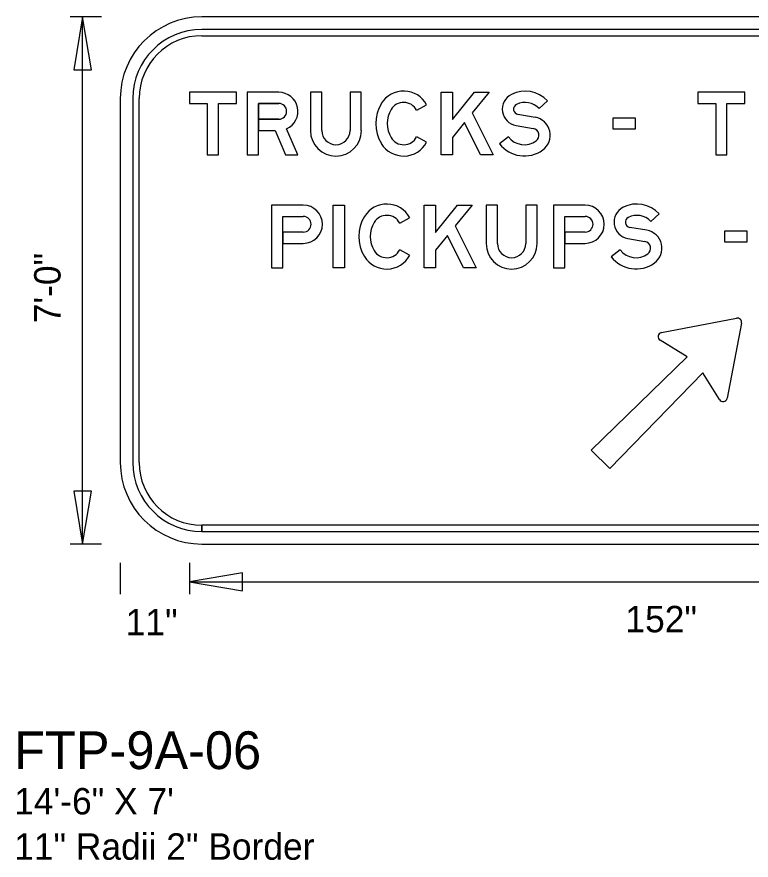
# Model space of a CAD drawing. Extents: x 0 to 770, y 0 to 495.
# Drawn here: x 391.7 to 488.9, y 9 to 120.7 of the extents above; entities that cross this region are included whole.
import ezdxf

# ---------------------------------------------------------------- set-up
doc = ezdxf.new("R2010")
doc.units = 0
for name, color, linetype in [('Dimension', 7, 'Continuous'), ('GSBWFill', 7, 'Continuous'), ('GSColorFill', 7, 'Continuous'), ('GSDims', 7, 'Continuous'), ('GSOutline', 7, 'Continuous'), ('TextStructures', 7, 'Continuous')]:
    doc.layers.add(name, color=color, linetype=linetype)

msp = doc.modelspace()

# ---------------------------------------------------------------- linework, layer by layer
at = {"layer": 'Dimension'}
for points in [[(400.45, 120.68), (399.27, 113.66), (401.64, 113.66)], [(400.45, 50.88), (401.64, 57.9), (399.27, 57.9)], [(414.58, 45.9), (421.6, 44.71), (421.6, 47.09)]]:
    msp.add_lwpolyline(points, close=True, dxfattribs=at)
at = {"layer": 'GSBWFill'}
for p, q in [((539.21, 120.68), (416.24, 120.68)), ((539.21, 119.01), (416.24, 119.01)), ((416.24, 118.18), (539.21, 118.18)), ((435.85, 110.71), (435.85, 105.62)), ((405.44, 109.87), (405.44, 61.68)), ((407.1, 109.87), (407.1, 61.68)), ((407.93, 61.68), (407.93, 109.87)), ((460.88, 108.54), (461.98, 109.56)), ((444.67, 108.32), (445.99, 109.02)), ((460.35, 107.37), (458.08, 107.75)), ((457.83, 106.28), (460.1, 105.9)), ((445.99, 104.08), (444.67, 104.78)), ((444.67, 104.78), (444.67, 104.78)), ((456.81, 104.78), (455.62, 103.87)), ((459.11, 95.75), (459.11, 90.66)), ((426.96, 94.25), (429.66, 94.25)), ((442.42, 93.36), (443.74, 94.07)), ((464.26, 94.25), (466.97, 94.25)), ((475.67, 93.59), (476.77, 94.61)), ((475.14, 92.42), (472.87, 92.8)), ((472.62, 91.32), (474.89, 90.94)), ((443.74, 89.12), (442.42, 89.83)), ((442.42, 89.83), (442.42, 89.83)), ((471.6, 89.83), (470.41, 88.92)), ((477.08, 78.87), (487.02, 80.78)), ((487.67, 80.14), (485.76, 70.19)), ((485.76, 70.19), (485.76, 70.19)), ((416.24, 52.54), (416.24, 53.38)), ((539.21, 53.38), (416.25, 53.38)), ((416.25, 53.38), (416.25, 52.54)), ((416.25, 52.54), (539.21, 52.54)), ((416.24, 50.88), (539.21, 50.88))]:
    msp.add_line(p, q, dxfattribs=at)
for points in [[(414.58, 109.21), (416.95, 109.21), (416.95, 102.4), (418.44, 102.4), (418.44, 109.21), (420.81, 109.21), (420.81, 110.71), (414.58, 110.71)], [(454.25, 110.71), (452.03, 107.96), (454.79, 102.4), (453.12, 102.4), (450.99, 106.69), (449.39, 104.72), (449.39, 102.4), (447.9, 102.4), (447.9, 110.71), (449.39, 110.71), (449.39, 107.09), (452.33, 110.71)], [(481.88, 109.21), (484.25, 109.21), (484.25, 102.4), (485.74, 102.4), (485.74, 109.21), (488.11, 109.21), (488.11, 110.71), (481.88, 110.71)], [(470.66, 107.3), (473.57, 107.3), (473.57, 105.8), (470.66, 105.8)], [(433.61, 87.44), (433.61, 95.75), (435.1, 95.75), (435.1, 87.44)], [(452.01, 95.75), (449.78, 93.01), (452.55, 87.44), (450.88, 87.44), (448.75, 91.73), (447.15, 89.77), (447.15, 87.44), (445.65, 87.44), (445.65, 95.75), (447.15, 95.75), (447.15, 92.14), (450.08, 95.75)], [(485.45, 92.34), (488.36, 92.34), (488.36, 90.85), (485.45, 90.85)]]:
    msp.add_lwpolyline(points, close=True, dxfattribs=at)
for points in [[(426.42, 110.71), (422.22, 110.71), (422.22, 102.4), (423.72, 102.4), (423.72, 109.21), (426.42, 109.21)], [(432.11, 105.62), (432.11, 110.71), (430.61, 110.71), (430.61, 105.62)], [(437.34, 105.62), (437.34, 110.71), (435.85, 110.71)], [(426.42, 107.13), (423.72, 107.13), (423.72, 105.64)], [(423.72, 105.64), (425.92, 105.64), (427.32, 102.4), (428.95, 102.4), (427.45, 105.86)], [(429.66, 95.75), (425.46, 95.75), (425.46, 87.44), (426.96, 87.44), (426.96, 94.25)], [(455.37, 90.66), (455.37, 95.75), (453.88, 95.75), (453.88, 90.66)], [(460.61, 90.66), (460.61, 95.75), (459.11, 95.75)], [(466.97, 95.75), (462.77, 95.75), (462.77, 87.44), (464.26, 87.44), (464.26, 94.25)], [(429.66, 92.18), (426.96, 92.18), (426.96, 90.68), (429.66, 90.68)], [(466.97, 92.18), (464.27, 92.18), (464.27, 90.68), (466.97, 90.68)], [(484.75, 70.01), (482.57, 73.57), (470.22, 60.88), (467.77, 63.33), (480.46, 75.68), (476.9, 77.86)]]:
    msp.add_lwpolyline(points, dxfattribs=at)
for centre, radius, start, end in [((416.24, 109.87), 10.8, 90, 180), ((416.24, 109.87), 9.14, 90, 180), ((416.24, 109.87), 8.31, 90, 180), ((459.03, 106.82), 4.03, 42.8759, 116.9123), ((458.2, 108.45), 2.2, 116.9123, 260.4087), ((458.2, 108.45), 0.706, 116.9123, 260.4087), ((459.03, 106.82), 2.53, 42.8759, 116.9123), ((459.94, 105), 2.41, 306.123, 80.4087), ((433.98, 105.62), 3.37, 180, 0), ((433.98, 105.62), 1.87, 180, 0), ((459.94, 105), 0.914, 306.123, 80.4087), ((458.92, 106.41), 4.15, 217.5895, 306.123), ((458.92, 106.41), 2.66, 217.5895, 306.123), ((429.66, 93.22), 2.53, 270, 90), ((472.99, 93.5), 2.2, 116.9123, 260.4087), ((473.82, 91.87), 4.03, 42.8759, 116.9123), ((429.66, 93.22), 1.04, 270, 90), ((472.99, 93.5), 0.706, 116.9123, 260.4087), ((473.82, 91.87), 2.53, 42.8759, 116.9123), ((474.73, 90.04), 2.41, 306.123, 80.4087), ((457.24, 90.66), 3.37, 180, 0), ((457.24, 90.66), 1.87, 180, 0), ((474.73, 90.04), 0.914, 306.123, 80.4087), ((473.71, 91.45), 2.66, 217.5895, 306.123), ((473.71, 91.45), 4.15, 217.5895, 306.123), ((487.13, 80.24), 0.551, 349.1228, 100.8772), ((477.18, 78.33), 0.551, 100.8772, 238.5281), ((485.22, 70.3), 0.551, 211.4719, 349.1228), ((416.24, 61.68), 10.8, 180, 270), ((416.24, 61.68), 9.14, 180, 270), ((416.24, 61.68), 8.31, 180, 270)]:
    msp.add_arc(centre, radius, start, end, dxfattribs=at)
for centre, major_axis, start_param, end_param in [((426.42, 108.17), (0, 2.53), 3.562504, 6.283185), ((442.94, 107.4), (0, 3.45), 5.201543, 7.308565), ((426.42, 108.17), (0, 1.04), 3.141593, 6.283185), ((444.35, 106.55), (0, 5.09), 1.025379, 2.116213), ((444.35, 106.55), (0, 3.59), 1.025379, 2.116213), ((442.94, 107.4), (0, 1.95), 5.201543, 7.308565), ((442.94, 105.7), (0, 3.45), 2.116213, 4.223235), ((442.94, 105.7), (0, 1.95), 2.116213, 4.223235), ((440.7, 92.45), (0, 3.45), 5.201543, 7.308565), ((466.97, 93.22), (0, 2.53), 3.141593, 6.283185), ((442.1, 91.6), (0, 5.09), 1.025379, 2.116213), ((440.7, 92.45), (0, 1.95), 5.201543, 7.308565), ((466.97, 93.22), (0, 1.04), 3.141593, 6.283185), ((442.1, 91.6), (0, 3.59), 1.025379, 2.116213), ((440.7, 90.74), (0, 1.95), 2.116213, 4.223235), ((440.7, 90.74), (0, 3.45), 2.116213, 4.223235)]:
    msp.add_ellipse(centre, major_axis=major_axis, ratio=0.999994, start_param=start_param, end_param=end_param, dxfattribs=at)
at = {"layer": 'GSColorFill'}
for p, q in [((435.85, 110.71), (435.85, 105.62)), ((460.88, 108.54), (461.98, 109.56)), ((444.67, 108.32), (445.99, 109.02)), ((460.35, 107.37), (458.08, 107.75)), ((457.83, 106.28), (460.1, 105.9)), ((445.99, 104.08), (444.67, 104.78)), ((444.67, 104.78), (444.67, 104.78)), ((456.81, 104.78), (455.62, 103.87)), ((459.11, 95.75), (459.11, 90.66)), ((426.96, 94.25), (429.66, 94.25)), ((442.42, 93.36), (443.74, 94.07)), ((464.26, 94.25), (466.97, 94.25)), ((475.67, 93.59), (476.77, 94.61)), ((475.14, 92.42), (472.87, 92.8)), ((472.62, 91.32), (474.89, 90.94)), ((443.74, 89.12), (442.42, 89.83)), ((442.42, 89.83), (442.42, 89.83)), ((471.6, 89.83), (470.41, 88.92)), ((477.08, 78.87), (487.02, 80.78)), ((487.67, 80.14), (485.76, 70.19)), ((485.76, 70.19), (485.76, 70.19))]:
    msp.add_line(p, q, dxfattribs=at)
for points in [[(414.58, 109.21), (416.95, 109.21), (416.95, 102.4), (418.44, 102.4), (418.44, 109.21), (420.81, 109.21), (420.81, 110.71), (414.58, 110.71)], [(454.25, 110.71), (452.03, 107.96), (454.79, 102.4), (453.12, 102.4), (450.99, 106.69), (449.39, 104.72), (449.39, 102.4), (447.9, 102.4), (447.9, 110.71), (449.39, 110.71), (449.39, 107.09), (452.33, 110.71)], [(481.88, 109.21), (484.25, 109.21), (484.25, 102.4), (485.74, 102.4), (485.74, 109.21), (488.11, 109.21), (488.11, 110.71), (481.88, 110.71)], [(470.66, 107.3), (473.57, 107.3), (473.57, 105.8), (470.66, 105.8)], [(433.61, 87.44), (433.61, 95.75), (435.1, 95.75), (435.1, 87.44)], [(452.01, 95.75), (449.78, 93.01), (452.55, 87.44), (450.88, 87.44), (448.75, 91.73), (447.15, 89.77), (447.15, 87.44), (445.65, 87.44), (445.65, 95.75), (447.15, 95.75), (447.15, 92.14), (450.08, 95.75)], [(485.45, 92.34), (488.36, 92.34), (488.36, 90.85), (485.45, 90.85)]]:
    msp.add_lwpolyline(points, close=True, dxfattribs=at)
for points in [[(426.42, 110.71), (422.22, 110.71), (422.22, 102.4), (423.72, 102.4), (423.72, 109.21), (426.42, 109.21)], [(432.11, 105.62), (432.11, 110.71), (430.61, 110.71), (430.61, 105.62)], [(437.34, 105.62), (437.34, 110.71), (435.85, 110.71)], [(426.42, 107.13), (423.72, 107.13), (423.72, 105.64)], [(423.72, 105.64), (425.92, 105.64), (427.32, 102.4), (428.95, 102.4), (427.45, 105.86)], [(429.66, 95.75), (425.46, 95.75), (425.46, 87.44), (426.96, 87.44), (426.96, 94.25)], [(455.37, 90.66), (455.37, 95.75), (453.88, 95.75), (453.88, 90.66)], [(460.61, 90.66), (460.61, 95.75), (459.11, 95.75)], [(466.97, 95.75), (462.77, 95.75), (462.77, 87.44), (464.26, 87.44), (464.26, 94.25)], [(429.66, 92.18), (426.96, 92.18), (426.96, 90.68), (429.66, 90.68)], [(466.97, 92.18), (464.27, 92.18), (464.27, 90.68), (466.97, 90.68)], [(484.75, 70.01), (482.57, 73.57), (470.22, 60.88), (467.77, 63.33), (480.46, 75.68), (476.9, 77.86)]]:
    msp.add_lwpolyline(points, dxfattribs=at)
for centre, radius, start, end in [((459.03, 106.82), 4.03, 42.8759, 116.9123), ((458.2, 108.45), 2.2, 116.9123, 260.4087), ((458.2, 108.45), 0.706, 116.9123, 260.4087), ((459.03, 106.82), 2.53, 42.8759, 116.9123), ((459.94, 105), 2.41, 306.123, 80.4087), ((433.98, 105.62), 3.37, 180, 0), ((433.98, 105.62), 1.87, 180, 0), ((459.94, 105), 0.914, 306.123, 80.4087), ((458.92, 106.41), 4.15, 217.5895, 306.123), ((458.92, 106.41), 2.66, 217.5895, 306.123), ((429.66, 93.22), 2.53, 270, 90), ((472.99, 93.5), 2.2, 116.9123, 260.4087), ((473.82, 91.87), 4.03, 42.8759, 116.9123), ((429.66, 93.22), 1.04, 270, 90), ((472.99, 93.5), 0.706, 116.9123, 260.4087), ((473.82, 91.87), 2.53, 42.8759, 116.9123), ((474.73, 90.04), 2.41, 306.123, 80.4087), ((457.24, 90.66), 3.37, 180, 0), ((457.24, 90.66), 1.87, 180, 0), ((474.73, 90.04), 0.914, 306.123, 80.4087), ((473.71, 91.45), 2.66, 217.5895, 306.123), ((473.71, 91.45), 4.15, 217.5895, 306.123), ((487.13, 80.24), 0.551, 349.1228, 100.8772), ((477.18, 78.33), 0.551, 100.8772, 238.5281), ((485.22, 70.3), 0.551, 211.4719, 349.1228)]:
    msp.add_arc(centre, radius, start, end, dxfattribs=at)
for centre, major_axis, start_param, end_param in [((426.42, 108.17), (0, 2.53), 3.562504, 6.283185), ((442.94, 107.4), (0, 3.45), 5.201543, 7.308565), ((426.42, 108.17), (0, 1.04), 3.141593, 6.283185), ((444.35, 106.55), (0, 5.09), 1.025379, 2.116213), ((444.35, 106.55), (0, 3.59), 1.025379, 2.116213), ((442.94, 107.4), (0, 1.95), 5.201543, 7.308565), ((442.94, 105.7), (0, 3.45), 2.116213, 4.223235), ((442.94, 105.7), (0, 1.95), 2.116213, 4.223235), ((440.7, 92.45), (0, 3.45), 5.201543, 7.308565), ((466.97, 93.22), (0, 2.53), 3.141593, 6.283185), ((442.1, 91.6), (0, 5.09), 1.025379, 2.116213), ((440.7, 92.45), (0, 1.95), 5.201543, 7.308565), ((466.97, 93.22), (0, 1.04), 3.141593, 6.283185), ((442.1, 91.6), (0, 3.59), 1.025379, 2.116213), ((440.7, 90.74), (0, 1.95), 2.116213, 4.223235), ((440.7, 90.74), (0, 3.45), 2.116213, 4.223235)]:
    msp.add_ellipse(centre, major_axis=major_axis, ratio=0.999994, start_param=start_param, end_param=end_param, dxfattribs=at)
at = {"layer": 'GSDims'}
for p, q in [((402.95, 120.68), (398.79, 120.68)), ((400.45, 50.88), (400.45, 120.68)), ((402.95, 50.88), (398.79, 50.88)), ((405.44, 48.39), (405.44, 44.24)), ((414.58, 48.39), (414.58, 44.24)), ((414.58, 48.39), (414.58, 44.24)), ((414.58, 45.9), (540.87, 45.9))]:
    msp.add_line(p, q, dxfattribs=at)
at = {"layer": 'GSOutline'}
for p, q in [((435.85, 110.71), (435.85, 105.62)), ((460.88, 108.54), (461.98, 109.56)), ((444.67, 108.32), (445.99, 109.02)), ((460.35, 107.37), (458.08, 107.75)), ((423.72, 107.13), (426.42, 107.13)), ((457.83, 106.28), (460.1, 105.9)), ((445.99, 104.08), (444.67, 104.78)), ((444.67, 104.78), (444.67, 104.78)), ((456.81, 104.78), (455.62, 103.87)), ((459.11, 95.75), (459.11, 90.66)), ((426.96, 94.25), (429.66, 94.25)), ((442.42, 93.36), (443.74, 94.07)), ((464.26, 94.25), (466.97, 94.25)), ((475.67, 93.59), (476.77, 94.61)), ((475.14, 92.42), (472.87, 92.8)), ((426.96, 90.68), (429.66, 90.68)), ((464.26, 90.68), (466.97, 90.68)), ((472.62, 91.32), (474.89, 90.94)), ((443.74, 89.12), (442.42, 89.83)), ((442.42, 89.83), (442.42, 89.83)), ((471.6, 89.83), (470.41, 88.92)), ((477.08, 78.87), (487.02, 80.78)), ((487.67, 80.14), (485.76, 70.19)), ((485.76, 70.19), (485.76, 70.19))]:
    msp.add_line(p, q, dxfattribs=at)
for points in [[(414.58, 109.21), (416.95, 109.21), (416.95, 102.4), (418.44, 102.4), (418.44, 109.21), (420.81, 109.21), (420.81, 110.71), (414.58, 110.71)], [(454.25, 110.71), (452.03, 107.96), (454.79, 102.4), (453.12, 102.4), (450.99, 106.69), (449.39, 104.72), (449.39, 102.4), (447.9, 102.4), (447.9, 110.71), (449.39, 110.71), (449.39, 107.09), (452.33, 110.71)], [(481.88, 109.21), (484.25, 109.21), (484.25, 102.4), (485.74, 102.4), (485.74, 109.21), (488.11, 109.21), (488.11, 110.71), (481.88, 110.71)], [(470.66, 107.3), (473.57, 107.3), (473.57, 105.8), (470.66, 105.8)], [(433.61, 87.44), (433.61, 95.75), (435.1, 95.75), (435.1, 87.44)], [(452.01, 95.75), (449.78, 93.01), (452.55, 87.44), (450.88, 87.44), (448.75, 91.73), (447.15, 89.77), (447.15, 87.44), (445.65, 87.44), (445.65, 95.75), (447.15, 95.75), (447.15, 92.14), (450.08, 95.75)], [(485.45, 92.34), (488.36, 92.34), (488.36, 90.85), (485.45, 90.85)]]:
    msp.add_lwpolyline(points, close=True, dxfattribs=at)
for points in [[(426.42, 110.71), (422.22, 110.71), (422.22, 102.4), (423.72, 102.4), (423.72, 105.64), (425.92, 105.64)], [(432.11, 105.62), (432.11, 110.71), (430.61, 110.71), (430.61, 105.62)], [(437.34, 105.62), (437.34, 110.71), (435.85, 110.71)], [(426.42, 109.21), (423.72, 109.21), (423.72, 107.13)], [(425.92, 105.64), (427.32, 102.4), (428.95, 102.4), (427.45, 105.86)], [(429.66, 95.75), (425.46, 95.75), (425.46, 87.44), (426.96, 87.44), (426.96, 90.68)], [(455.37, 90.66), (455.37, 95.75), (453.88, 95.75), (453.88, 90.66)], [(460.61, 90.66), (460.61, 95.75), (459.11, 95.75)], [(466.97, 95.75), (462.77, 95.75), (462.77, 87.44), (464.26, 87.44), (464.26, 90.68)], [(429.66, 92.18), (426.96, 92.18), (426.96, 94.25)], [(466.97, 92.18), (464.26, 92.18), (464.26, 94.25)], [(484.75, 70.01), (482.57, 73.57), (470.22, 60.88), (467.77, 63.33), (480.46, 75.68), (476.9, 77.86)]]:
    msp.add_lwpolyline(points, dxfattribs=at)
for centre, radius, start, end in [((459.03, 106.82), 4.03, 42.8759, 116.9123), ((458.2, 108.45), 2.2, 116.9123, 260.4087), ((458.2, 108.45), 0.706, 116.9123, 260.4087), ((459.03, 106.82), 2.53, 42.8759, 116.9123), ((459.94, 105), 2.41, 306.123, 80.4087), ((433.98, 105.62), 3.37, 180, 0), ((433.98, 105.62), 1.87, 180, 0), ((459.94, 105), 0.914, 306.123, 80.4087), ((458.92, 106.41), 4.15, 217.5895, 306.123), ((458.92, 106.41), 2.66, 217.5895, 306.123), ((429.66, 93.22), 2.53, 270, 90), ((472.99, 93.5), 2.2, 116.9123, 260.4087), ((473.82, 91.87), 4.03, 42.8759, 116.9123), ((429.66, 93.22), 1.04, 270, 90), ((472.99, 93.5), 0.706, 116.9123, 260.4087), ((473.82, 91.87), 2.53, 42.8759, 116.9123), ((474.73, 90.04), 2.41, 306.123, 80.4087), ((457.24, 90.66), 3.37, 180, 0), ((457.24, 90.66), 1.87, 180, 0), ((474.73, 90.04), 0.914, 306.123, 80.4087), ((473.71, 91.45), 2.66, 217.5895, 306.123), ((473.71, 91.45), 4.15, 217.5895, 306.123), ((487.13, 80.24), 0.551, 349.1228, 100.8772), ((477.18, 78.33), 0.551, 100.8772, 238.5281), ((485.22, 70.3), 0.551, 211.4719, 349.1228)]:
    msp.add_arc(centre, radius, start, end, dxfattribs=at)
for centre, major_axis, start_param, end_param in [((426.42, 108.17), (0, 2.53), 3.562504, 6.283185), ((442.94, 107.4), (0, 3.45), 5.201543, 7.308565), ((426.42, 108.17), (0, 1.04), 3.141593, 6.283185), ((444.35, 106.55), (0, 5.09), 1.025379, 2.116213), ((444.35, 106.55), (0, 3.59), 1.025379, 2.116213), ((442.94, 107.4), (0, 1.95), 5.201543, 7.308565), ((442.94, 105.7), (0, 3.45), 2.116213, 4.223235), ((442.94, 105.7), (0, 1.95), 2.116213, 4.223235), ((440.7, 92.45), (0, 3.45), 5.201543, 7.308565), ((466.97, 93.22), (0, 2.53), 3.141593, 6.283185), ((442.1, 91.6), (0, 5.09), 1.025379, 2.116213), ((440.7, 92.45), (0, 1.95), 5.201543, 7.308565), ((466.97, 93.22), (0, 1.04), 3.141593, 6.283185), ((442.1, 91.6), (0, 3.59), 1.025379, 2.116213), ((440.7, 90.74), (0, 1.95), 2.116213, 4.223235), ((440.7, 90.74), (0, 3.45), 2.116213, 4.223235)]:
    msp.add_ellipse(centre, major_axis=major_axis, ratio=0.999994, start_param=start_param, end_param=end_param, dxfattribs=at)

# ---------------------------------------------------------------- texts
at = {"layer": 'TextStructures'}
msp.add_text('7\'-0"', height=3.5, rotation=90, dxfattribs=at).set_placement((397.53, 80.11))
for s, height, p in [('152"', 3.5, (472.3, 39.2)), ('11"', 3.5, (406.16, 38.8)), ('FTP-9A-06', 5, (391.39, 21.09)), ('14\'-6" X 7\' ', 3.5, (391.39, 15.09)), ('11" Radii 2" Border', 3.5, (391.39, 9.09))]:
    msp.add_text(s, height=height, dxfattribs=at).set_placement(p)

doc.saveas('drawing.dxf')
